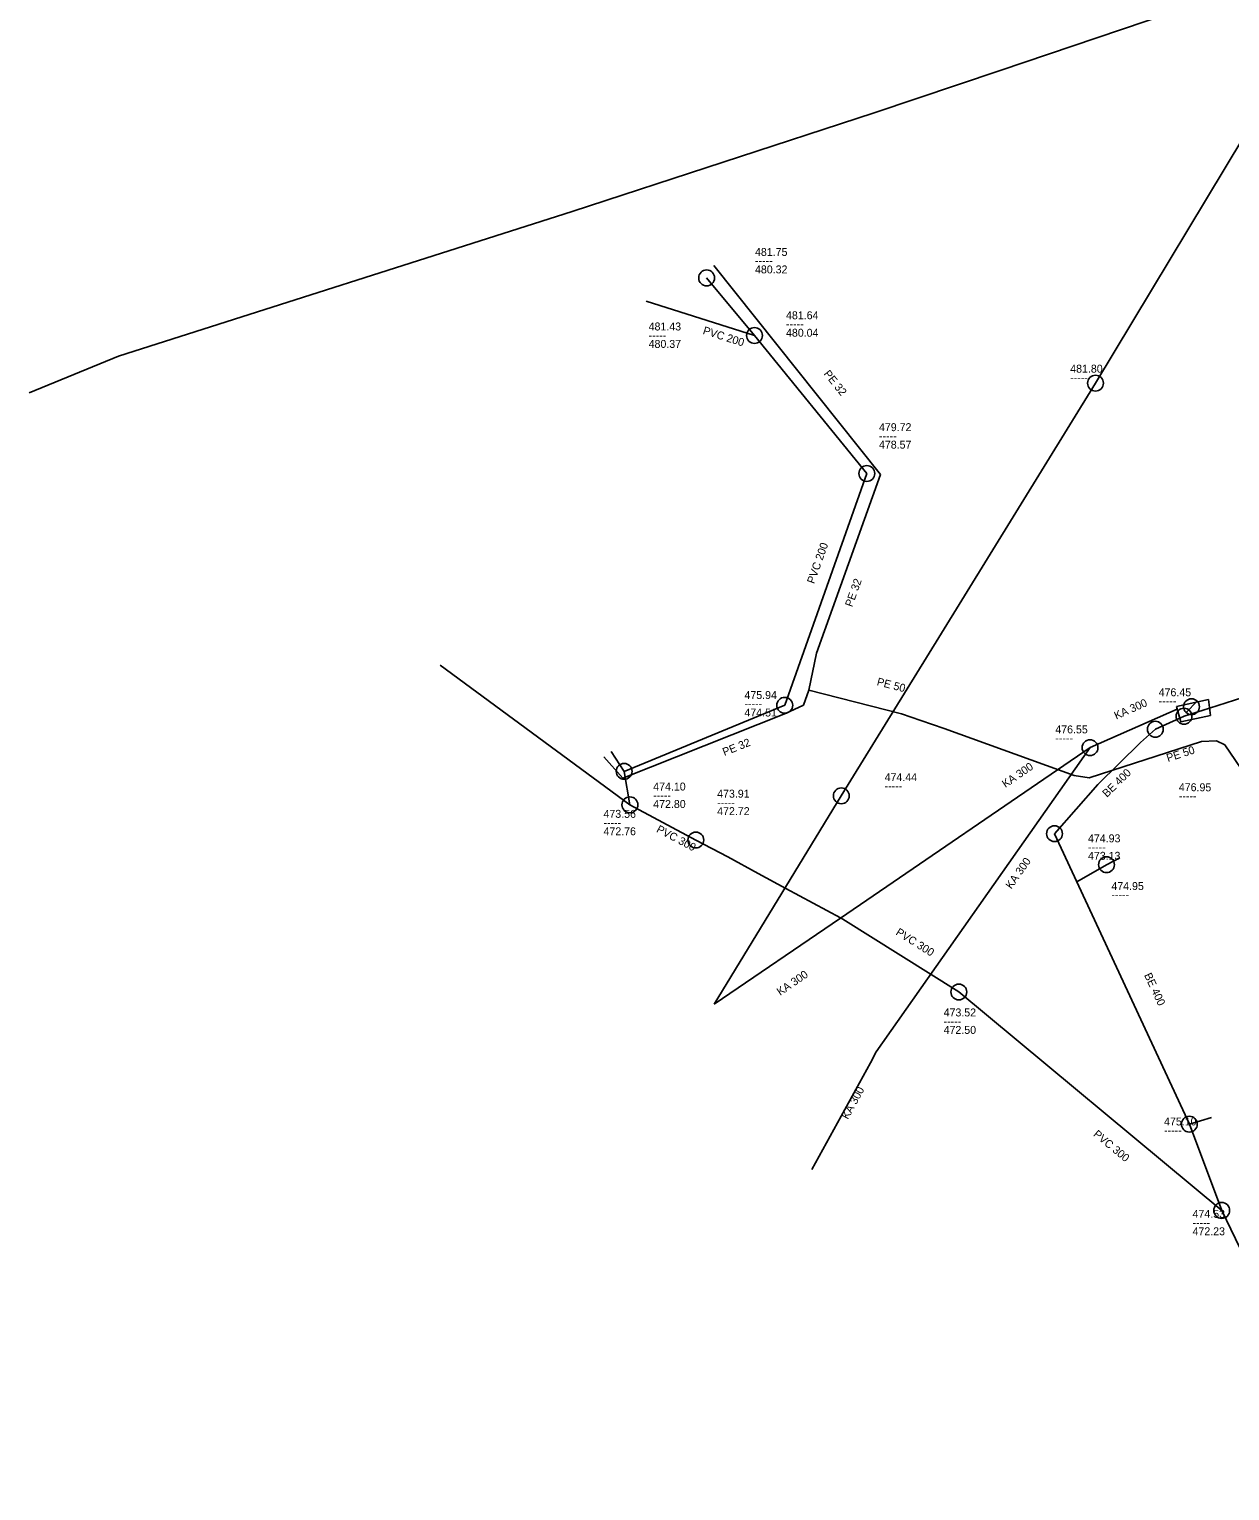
# Model space of a CAD drawing. Extents: x -685576 to -685179, y -1163336 to -1162895.
# Drawn here: x -685575.9 to -685424.5, y -1163249.3 to -1163065.1 of the extents above; entities that cross this region are included whole.
import ezdxf

# ---------------------------------------------------------------- set-up
doc = ezdxf.new("R2010")
doc.units = 0
doc.layers.add('Level 0', color=7, linetype='Continuous')

msp = doc.modelspace()

# ---------------------------------------------------------------- linework, layer by layer
at = {"layer": 'Level 0'}
for p, q in [((-685453.48, -1163070.32), (-685421.84, -1163059.63)), ((-685415.3, -1163066.26), (-685441.48, -1163109.74)), ((-685469.36, -1163075.69), (-685453.48, -1163070.32)), ((-685507.45, -1163088.13), (-685469.36, -1163075.69)), ((-685564.65, -1163106.35), (-685507.45, -1163088.13)), ((-685468.58, -1163121.27), (-685489.59, -1163094.93)), ((-685490.5, -1163096.48), (-685484.47, -1163103.74)), ((-685498.14, -1163099.41), (-685484.47, -1163103.74)), ((-685484.47, -1163103.74), (-685470.3, -1163121.13)), ((-685575.9, -1163110.98), (-685564.65, -1163106.35)), ((-685441.48, -1163109.74), (-685461.23, -1163141.8)), ((-685470.3, -1163121.13), (-685480.65, -1163150.34)), ((-685476.64, -1163143.78), (-685468.58, -1163121.27)), ((-685461.23, -1163141.8), (-685473.52, -1163161.75)), ((-685477.6, -1163148.45), (-685476.64, -1163143.78)), ((-685524.09, -1163145.29), (-685500.17, -1163162.89)), ((-685478.29, -1163150.31), (-685477.6, -1163148.45)), ((-685465.95, -1163151.42), (-685477.6, -1163148.45)), ((-685480.65, -1163150.34), (-685500.89, -1163158.67)), ((-685480.57, -1163151.37), (-685478.29, -1163150.31)), ((-685431.26, -1163150.5), (-685427.24, -1163149.59)), ((-685430.73, -1163152.41), (-685431.26, -1163150.5)), ((-685430.06, -1163151.24), (-685428.65, -1163149.84)), ((-685427.24, -1163149.59), (-685426.99, -1163151.64)), ((-685421.86, -1163149.04), (-685427.1, -1163150.7)), ((-685501.08, -1163159.52), (-685480.57, -1163151.37)), ((-685463.51, -1163152.26), (-685465.95, -1163151.42)), ((-685460.57, -1163153.27), (-685463.51, -1163152.26)), ((-685431.17, -1163150.84), (-685442.16, -1163155.68)), ((-685430.85, -1163151.97), (-685433.93, -1163153.36)), ((-685430.31, -1163151.72), (-685430.85, -1163151.97)), ((-685426.99, -1163151.64), (-685430.73, -1163152.41)), ((-685427.1, -1163150.7), (-685430.31, -1163151.72)), ((-685444.15, -1163159.2), (-685460.57, -1163153.27)), ((-685433.93, -1163153.36), (-685435.79, -1163155.04)), ((-685502.54, -1163156.16), (-685500.89, -1163158.67)), ((-685442.16, -1163155.68), (-685473.63, -1163177.15)), ((-685442.16, -1163155.68), (-685469.11, -1163194.02)), ((-685428.11, -1163154.92), (-685442.27, -1163159.47)), ((-685435.79, -1163155.04), (-685441.2, -1163160.33)), ((-685426.2, -1163154.83), (-685428.11, -1163154.92)), ((-685425.17, -1163155.33), (-685426.2, -1163154.83)), ((-685420.25, -1163162.58), (-685425.17, -1163155.33)), ((-685503.45, -1163156.85), (-685501.08, -1163159.52)), ((-685500.89, -1163158.67), (-685500.17, -1163162.89)), ((-685442.27, -1163159.47), (-685444.15, -1163159.2)), ((-685441.2, -1163160.33), (-685446.64, -1163166.52)), ((-685500.17, -1163162.89), (-685491.86, -1163167.32)), ((-685473.52, -1163161.75), (-685489.56, -1163188.02)), ((-685446.64, -1163166.52), (-685429.64, -1163203.13)), ((-685491.86, -1163167.32), (-685487.84, -1163169.43)), ((-685487.84, -1163169.43), (-685483.99, -1163171.52)), ((-685440.08, -1163170.43), (-685443.82, -1163172.57)), ((-685438.42, -1163169.57), (-685440.08, -1163170.43)), ((-685483.99, -1163171.52), (-685480.5, -1163173.42)), ((-685480.5, -1163173.42), (-685473.62, -1163177.13)), ((-685473.63, -1163177.15), (-685489.56, -1163188.02)), ((-685473.62, -1163177.13), (-685473.33, -1163177.29)), ((-685473.33, -1163177.29), (-685458.7, -1163186.47)), ((-685458.7, -1163186.47), (-685425.56, -1163214)), ((-685469.11, -1163194.02), (-685469.86, -1163195.39)), ((-685469.86, -1163195.39), (-685477.25, -1163208.86)), ((-685426.85, -1163202.27), (-685429.64, -1163203.13)), ((-685429.64, -1163203.13), (-685425.56, -1163214)), ((-685425.56, -1163214), (-685408.59, -1163249.33))]:
    msp.add_line(p, q, dxfattribs=at)
for centre in [(-685490.5, -1163096.48), (-685484.47, -1163103.74), (-685441.48, -1163109.74), (-685470.3, -1163121.13), (-685480.65, -1163150.34), (-685429.37, -1163150.52), (-685433.93, -1163153.36), (-685430.31, -1163151.72), (-685442.16, -1163155.68), (-685500.89, -1163158.67), (-685473.52, -1163161.75), (-685500.17, -1163162.89), (-685491.86, -1163167.32), (-685446.64, -1163166.52), (-685440.08, -1163170.43), (-685458.7, -1163186.47), (-685429.64, -1163203.13), (-685425.56, -1163214)]:
    msp.add_circle(centre, 1, dxfattribs=at)

# ---------------------------------------------------------------- texts
for s, p in [('481.75', (-685484.4, -1163093.71)), ('480.32', (-685484.4, -1163095.91)), ('-----', (-685484.4, -1163094.81)), ('481.64', (-685480.49, -1163101.69)), ('481.43', (-685497.81, -1163103.1)), ('-----', (-685480.49, -1163102.79)), ('480.37', (-685497.81, -1163105.3)), ('-----', (-685497.81, -1163104.2)), ('480.04', (-685480.49, -1163103.89)), ('481.80', (-685444.66, -1163108.42)), ('-----', (-685444.66, -1163109.52)), ('479.72', (-685468.77, -1163115.79)), ('478.57', (-685468.77, -1163117.99)), ('-----', (-685468.77, -1163116.89)), ('475.94', (-685485.73, -1163149.55)), ('476.45', (-685433.51, -1163149.2)), ('-----', (-685485.73, -1163150.65)), ('-----', (-685433.51, -1163150.3)), ('474.51', (-685485.73, -1163151.75)), ('476.55', (-685446.54, -1163153.88)), ('-----', (-685446.54, -1163154.98)), ('474.44', (-685468.06, -1163159.9)), ('474.10', (-685497.23, -1163161.08)), ('473.91', (-685489.17, -1163161.98)), ('-----', (-685468.06, -1163161)), ('473.56', (-685503.5, -1163164.52)), ('472.80', (-685497.23, -1163163.28)), ('-----', (-685497.23, -1163162.18)), ('472.72', (-685489.17, -1163164.18)), ('-----', (-685489.17, -1163163.08)), ('-----', (-685503.5, -1163165.62)), ('472.76', (-685503.5, -1163166.72)), ('474.93', (-685442.42, -1163167.61)), ('473.13', (-685442.42, -1163169.81)), ('-----', (-685442.42, -1163168.71)), ('474.95', (-685439.47, -1163173.62)), ('-----', (-685439.47, -1163174.72)), ('473.52', (-685460.62, -1163189.55)), ('472.50', (-685460.62, -1163191.75)), ('-----', (-685460.62, -1163190.65)), ('475.10', (-685432.83, -1163203.29)), ('-----', (-685432.83, -1163204.39)), ('474.53', (-685429.24, -1163214.93)), ('472.23', (-685429.24, -1163217.13)), ('-----', (-685429.24, -1163216.03))]:
    msp.add_text(s, height=1, dxfattribs=at).set_placement(p)
for s, rotation, p in [('PVC 200', 342.424, (-685491.05, -1163103.52)), ('PE 32', 308.577, (-685475.8, -1163108.59)), ('PVC 200', 70.489, (-685476.94, -1163135.1)), ('PE 32', 70.299, (-685472.15, -1163138.02)), ('PE 50', 345.698, (-685469.11, -1163147.8)), ('KA 300', 23.776, (-685438.86, -1163152.15)), ('PE 32', 21.671, (-685488.26, -1163156.74)), ('PE 50', 17.814, (-685432.34, -1163157.49)), ('KA 300', 34.303, (-685452.84, -1163160.77)), ('BE 400', 44.357, (-685440.03, -1163162.01)), ('476.95', 359.456, (-685430.97, -1163161.15)), ('-----', 359.456, (-685430.97, -1163162.25)), ('PVC 300', 331.938, (-685496.92, -1163166.26)), ('KA 300', 54.896, (-685452.08, -1163173.57)), ('PVC 300', 327.893, (-685466.74, -1163179.19)), ('KA 300', 34.308, (-685481.23, -1163186.97)), ('BE 400', 294.908, (-685435.37, -1163184.34)), ('KA 300', 61.25, (-685472.68, -1163202.61)), ('PVC 300', 320.283, (-685441.83, -1163204.54))]:
    msp.add_text(s, height=1, rotation=rotation, dxfattribs=at).set_placement(p)

doc.saveas('drawing.dxf')
